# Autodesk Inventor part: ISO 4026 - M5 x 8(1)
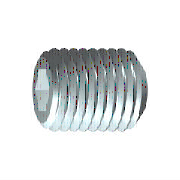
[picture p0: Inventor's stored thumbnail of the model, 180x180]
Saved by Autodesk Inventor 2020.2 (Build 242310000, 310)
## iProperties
Created: 2019-01
Part Number: ISO 4026 - M5 x 8(1)
Material: Edelstahl, 440C
Description: Innensechskant-Gewindestifte mit Kegelstumpf
Document SubType Name: Modeling
Standard: ISO 4026
Designer: lutzd
Standard Revision: Third edition 2003-12-01
Standards Organization: ISO
Language: de-DE
Size Designation: M5 x 8
Categories: <MemberInstance><Categories><Category DisplayName="Verbindungselemente" InternalName="e4da775c-781d-43d5-af7c-5136215cf5a6" Mnemonic="FSTN"><Category DisplayNam
Mass: 1.05042 g
Surface Area: 1.82729 cm^2
Volume: 0.135538 cm^3
Density: 7.75 g/cm^3
Appearance: Semi-Polished(3)
IsCustomPart: 0
Author: lutzd
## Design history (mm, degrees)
sketch "Skizze1"
  geometry: L1 (0, 0)-(4.167, 0); L2 (8, 1.443)-(8, 2.5); L3 (8, 2.5)-(0, 2.5); L4 (8, 1.443)-(5, 1.443); L5 (5, 1.443)-(4.167, 0); L6 (0, -0.5)-(0, 3) reference; L7 (0, 2.5)-(0, 0)
  constraints: 13 end point, 3 parallel, 1 collinear, 1 perpendicular, 1 point on line
  dimensions: "d0" = 3 distance of L2.start L4.end (= INTI); "d1" = 60 deg angle of L5 L1; "d2" = 5 diameter of L3 L1 (= NND); "d3" = 2.88675 diameter of L4 L1 (= 1.1547 x SW); "d5" = 8 distance from line of L2 L3.end (= NLG)
revolve "Körper" sketch "Skizze1" stored, may be unused: angle "d6" = 90 deg
sketch "Skizze2"
  geometry: L1 (-0.722, 1.25)-(0.722, 1.25); L2 (0.722, 1.25)-(1.443, 0); L3 (1.443, 0)-(0.722, -1.25); L4 (0.722, -1.25)-(-0.722, -1.25); L5 (-0.722, -1.25)-(-1.443, 0); L6 (-1.443, 0)-(-0.722, 1.25); A1 r 1.443 centre (0, 0) between (-0.722, 1.25) and (0.722, 1.25) reference; 2 further points
  constraints: 12 end point, 2 point on circle, 1 coincident, 1 horizontal, 11 other
extrude "Loch" join sketch "Skizze2" taper "d9" = 0 deg; stored distance "d21" = 10
workaxis "Work Axis1"
workplane "Work Plane1"
body "Solid1"
chamfer "Fase1" distance "d7" = 0.49076 (= -0.5 x GD1 + 0.5 x NND); stored, may be unused: angle "d8" = 45 deg (= FAWI), second distance "d29" = 0.49076 (= -0.5 x GD1 + 0.5 x NND)
feature "Gewinde" dims "d11" = 8 (= NLG), "d12" = 0
chamfer "Fase2" distance "d13" = 0.49076 (= -0.5 x GD1 + 0.5 x NND); stored, may be unused: angle "d14" = 45 deg (= FAWI), second distance "d30" = 0.49076 (= -0.5 x GD1 + 0.5 x NND)
other parameters: "NND" = 5 [user parameter; used in 5 equation terms], "NLG" = 8 [user parameter; used in 2 equation terms], "INTI" = 3 [user parameter; used in 1 equation term], "FAWI" = 45 deg [user parameter; used in 2 equation terms], "SW" = 2.5 [user parameter; used in 2 equation terms], "GD1" = 4.01848 (= THREADDIA - 1.2269 x PTC) [user parameter; used in 4 equation terms], "d4" = 0, "FAWI1" = 45 deg [user parameter], "d15" = 0, "d31" = 0, "GUL" = 0.49076 (= 0.61345 x PTC) [user parameter], "SPD" = 3.5 [user parameter], "SEWI" = 90 deg [user parameter], "TOA" = 30 deg [user parameter], "THREADDIA" = 5 [user parameter; used in 1 equation term], "TPU" = 12.5 (computed from PTC) [user parameter], "PTC" = 0.8 [user parameter; used in 4 equation terms], "GAL" = 0.49076 (= 0.61345 x PTC) [user parameter], "E0" = 2.8875 (= 1.155 x SW) [user parameter]
